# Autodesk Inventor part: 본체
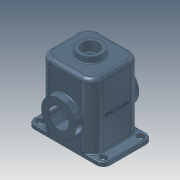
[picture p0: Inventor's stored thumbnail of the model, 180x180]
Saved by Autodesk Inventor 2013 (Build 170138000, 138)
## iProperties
Company: 한국ATC센터
Created: 2014-10
Part Number: 본체
Document SubType Name: Modeling
Designer: 한국ATC센터
Density: 2.71 g/cm^3
Material: 알루미늄 6061
Mass: 3285.46 g
Surface Area: 2358.49 cm^2
Volume: 1212.35 cm^3
Author: KYOUNG IL JANG
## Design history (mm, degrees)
sketch "스케치1"
  geometry: L1 (-70, 65)-(70, 65); L2 (70, 65)-(70, -65); L3 (70, -65)-(-70, -65); L4 (-70, -65)-(-70, 65); 3 further points
  constraints: 8 end point, 2 midpoint, 2 parallel, 1 horizontal, 1 horizontal alignment, 1 perpendicular, 1 vertical alignment
  dimensions: "d0" = 140 distance of L2.end L3.end; "d68" = 130 distance of L3.end L1.start
extrude "돌출1" new body sketch "스케치1" distance "d1" = 180; taper "d2" = 0 deg
fillet "모깎기1" dims "d3" = 20
feature "쉘1" dims "d4" = 10
sketch "스케치2"
  geometry: L1 (-70, 45)-(-70, -45) reference; L2 (-50, -65)-(-82, -65); L3 (-82, 65)-(-50, 65); L4 (-85, 57)-(-82, 57); L5 (-82, 41)-(-85, 41); L6 (-100, 47)-(-100, -47); A1 r 20 centre (-50, 45) between (-50, 65) and (-70, 45) reference; A2 r 20 centre (-50, -45) between (-70, -45) and (-50, -65) reference; A3 r 8 centre (-82, 49) between (-82, 41) and (-82, 57); A4 r 8 centre (-85, 49) between (-85, 57) and (-85, 41); A5 r 18 centre (-82, 47) between (-82, 65) and (-100, 47); A6 r 18 centre (-82, -47) between (-100, -47) and (-82, -65); 1 further point
  constraints: 10 end point, 9 tangent, 8 point on circle, 4 centre point, 2 parallel, 2 perpendicular, 1 equal radius
  dimensions: "d6" = 49 vertical distance of point (0, 0) A3.centre; "d8" = 16 distance between parallel lines of L4 L5; "d64" = 18 radius of A5; "d65" = 12 distance from line of A3.centre L1; "d66" = 30 distance between parallel lines of L6 L1; "d67" = 3 distance of A4.centre A3.centre
extrude "돌출2" join sketch "스케치2" distance "d9" = 10; taper "d10" = 0 deg
extrude "돌출3" cut sketch "스케치2" stored distance "d11" = 10; taper "d12" = 0 deg
sketch "스케치3"
  geometry: L1 (-65, 0)-(-65, 180) reference; L2 (-55, 0)-(-55, 170) reference; L3 (-83, 75)-(-51, 75); L4 (45, 0)-(-45, 0) reference; L5 (-83, 75)-(-83, 120.5); L6 (-83, 120.5)-(-55, 120.5); L7 (-55, 120.5)-(-51, 116.5); L8 (-51, 116.5)-(-51, 75); 2 further points
  constraints: 10 end point, 4 perpendicular, 1 point on line
  dimensions: "d13" = 75 distance between parallel lines of L3 L4; "d14" = 18 distance from line of L1 L3.start; "d15" = 4 distance from line of L3.end L2; "d16" = 91 diameter of L6 L3; "d17" = 135 deg angle of L7 L2
revolve "회전1" sketch "스케치3" stored, may be unused: angle "d18" = 90 deg
sketch "스케치4"
  geometry: C1 r 45.5 at (0, 0) reference; 2 further points
  constraints: 1 vertical alignment
  dimensions: "d19" = 35 distance of C1.centre point (0, 35)
hole "구멍1" sketch "스케치4" at (0, 35) diameter "d20" = 3.459; stored, may be unused: countersink angle "d24" = 90 deg, drill point angle "d26" = 118 deg; dims "d21" = 13, "d22" = 4, "d23" = 2, "d25" = 16
fillet "모깎기2" dims "d30" = 3
hole "구멍2" diameter "d33" = 52; stored, may be unused: countersink angle "d37" = 90 deg, drill point angle "d39" = 118 deg; dims "d31" = 10, "d32" = 10, "d34" = 13, "d35" = 4, "d36" = 2, "d38" = 16
sketch "스케치5"
  geometry: C1 r 31 at (0, 0); 1 further point
  constraints: 1 centre point, 1 coincident
  dimensions: "d40" = 62 diameter of C1
extrude "돌출4" join sketch "스케치5" distance "d41" = 15; taper "d42" = 0 deg
hole "구멍3" diameter "d45" = 43; stored, may be unused: countersink angle "d49" = 90 deg, drill point angle "d51" = 118 deg; dims "d43" = 10, "d44" = 10, "d46" = 13, "d47" = 4, "d48" = 2, "d50" = 16
fillet "모깎기3" dims "d52" = 3
fillet "모깎기4" dims "d53" = 3
chamfer "모따기1" distance "d55" = 1; stored, may be unused: second distance "d56" = 2, angle "d57" = 45 deg
sketch "스케치6"
  geometry: 2 further points
  constraints: 1 vertical alignment, 1 other
  dimensions: "d71" = 90 distance of point (0, 0) point (0, 90)
feature "엠보싱2" sketch "스케치6" dims "d0" = 140, "d68" = 130, "d72" = 1, "d73" = 0
fillet "모깎기6" dims "d74" = 10
sketch "스케치7"
  geometry: C1 r 15 at (0, 0); C2 r 21.5 at (0, 0) reference; C3 r 25 at (0, 0); 1 further point
  constraints: 2 centre point, 2 coincident
  dimensions: "d61" = 30 diameter of C1; "d75" = 50 diameter of C3
extrude "돌출5" join sketch "스케치7" distance "d62" = 10; taper "d63" = 0 deg
feature "면 이동1" dims "d76" = 1
fillet "모깎기7" dims "d77" = 3
node "솔리드1"
mirror "대칭1"
mirror "대칭2"
pattern_circular "원형 패턴1" dims angle "d28" = 360 deg
mirror "대칭3"
